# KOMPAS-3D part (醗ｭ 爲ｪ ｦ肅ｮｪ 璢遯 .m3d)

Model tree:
1. Эскиз:1
2. Операция выдавливания:1
     Расстояние 1 = 15; Угол 1 = 8
3. Эскиз:2
4. Вырезать элемент выдавливания:1
     Расстояние 1 = 20
5. Эскиз:3
6. Вырезать элемент выдавливания:2
     Расстояние 1 = 2
7. Фаска:1
     Угол = 45; Длина 1 = 1; Длина 2 = 1
8. Скругление:1
     Радиус = 1
